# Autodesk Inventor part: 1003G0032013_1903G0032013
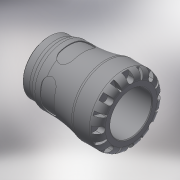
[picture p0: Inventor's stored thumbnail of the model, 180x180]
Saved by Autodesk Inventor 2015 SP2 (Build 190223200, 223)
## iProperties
Created: 2016-12
Part Number: 1003G0032013_1903G0032013
Material: Generic
Description: PLASSON FEMALE ADAPTOR 32x1 1/4" SERIES 1
Document SubType Name: Modeling
Designer: KIM
Mass: 107.226 g
Surface Area: 283.372 cm^2
Volume: 107.226 cm^3
Density: 1 g/cm^3
Appearance: Default
Author: KIM
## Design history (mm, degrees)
derived "1003G.ipt"
feature "Solid1::1003G.ipt"
tag "TaggingFeature1"
body "Solid1"
other parameters: "d1" = 26.88, "d2" = 32, "d4" = 58, "d6" = 64, "d8" = 49.3, "d13" = 7.2, "d14" = 7.2, "d15" = 0, "d17" = 360 deg, "d19" = 8 deg, "d20" = 0.64, "d21" = 0.64, "d22" = 8 deg, "d24" = 0, "d26" = 360 deg, "d32" = 5.8, "d33" = 5.8, "d39" = 1.16856, "d42" = 38.952, "d43" = 45.24, "d46" = 2.66667, "d47" = 19, "d48" = 37.0044, "d50" = 2.31, "d51" = 0.58, "d54" = 11.2, "d55" = 7.04, "d57" = 14.112, "d58" = 0, "d68" = 360 deg, "d72" = 0.64, "d74" = 0, "d76" = 9.52, "d_" = 32, "E_" = 58, "l_" = 64, "G_" = 38.952, "l_2" = 19, "d9" = 9, "d11" = 58, "d49" = 7
